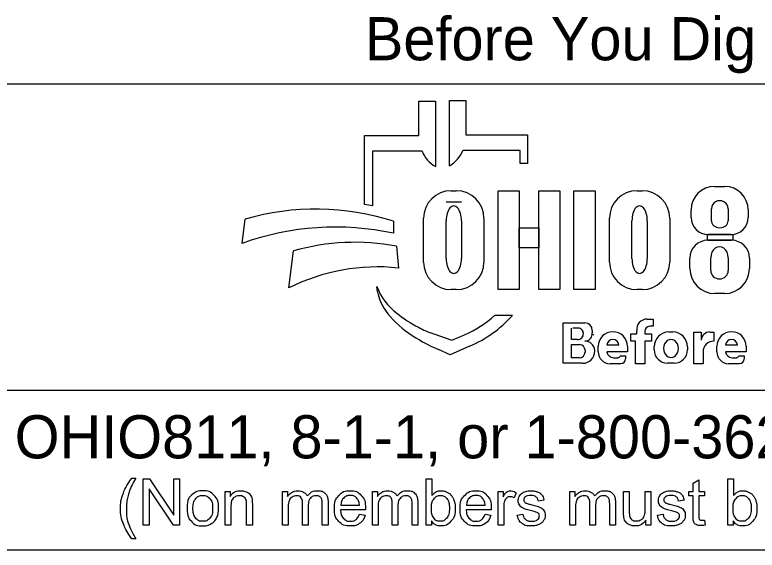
# Model space of a CAD drawing. Extents: x 0 to 34, y 0 to 22.
# Drawn here: x 2.423 to 4.831, y 2.143 to 3.88 of the extents above; entities that cross this region are included whole.
import ezdxf

# ---------------------------------------------------------------- set-up
doc = ezdxf.new("R2010")
doc.units = 0
doc.layers.add('SH_Data', color=7, linetype='Continuous')
doc.layers.add('SH_Text', color=7, linetype='Continuous')

msp = doc.modelspace()

# ---------------------------------------------------------------- linework, layer by layer
at = {"layer": 'SH_Data'}
for p, q in [((2.3775, 3.6553), (6.6275, 3.6553)), ((6.6275, 2.6607), (2.3775, 2.6607)), ((6.6275, 2.1428), (2.3775, 2.1428))]:
    msp.add_line(p, q, dxfattribs=at)
at = {"layer": 'SH_Text'}
for p, q in [((3.7335, 3.4883), (3.7335, 3.5998)), ((3.7335, 3.5998), (3.7872, 3.5998)), ((3.7872, 3.5998), (3.7872, 3.3877)), ((3.8329, 3.39), (3.8329, 3.6021)), ((3.8329, 3.6021), (3.8865, 3.6021)), ((3.8865, 3.6021), (3.8865, 3.4906)), ((3.5576, 3.2644), (3.5576, 3.4883)), ((3.5576, 3.4883), (3.7335, 3.4883)), ((3.8865, 3.4906), (4.0857, 3.4906)), ((4.0857, 3.4906), (4.0857, 3.3968)), ((3.5828, 3.4369), (3.5828, 3.26)), ((3.7439, 3.4369), (3.5828, 3.4369)), ((4.0625, 3.4392), (3.8761, 3.4392)), ((4.0625, 3.3968), (4.0625, 3.4392)), ((4.0857, 3.3968), (4.0625, 3.3968)), ((3.8385, 3.3091), (3.8551, 3.3091)), ((4.4416, 3.3091), (4.4581, 3.3091)), ((4.6931, 3.3231), (4.7258, 3.3231)), ((3.8718, 3.2721), (3.822, 3.2721)), ((4.6168, 3.2225), (4.6168, 3.2468)), ((4.683, 3.2111), (4.683, 3.2504)), ((4.7371, 3.2504), (4.7371, 3.2111)), ((4.8022, 3.2468), (4.8022, 3.2225)), ((3.1602, 3.1381), (3.1696, 3.2162)), ((3.6509, 3.2097), (3.6509, 3.1709)), ((3.7491, 3.0776), (3.7491, 3.2196)), ((3.822, 3.089), (3.822, 3.2114)), ((3.8718, 3.2114), (3.8718, 3.089)), ((3.9445, 3.2196), (3.9445, 3.0776)), ((4.3521, 3.0776), (4.3521, 3.2196)), ((4.425, 3.089), (4.425, 3.2114)), ((4.4748, 3.2114), (4.4748, 3.089)), ((4.5476, 3.2196), (4.5476, 3.0776)), ((4.7462, 3.1665), (4.6728, 3.1665)), ((4.671, 3.1482), (4.7483, 3.1482)), ((3.312, 2.9936), (3.3267, 3.1137)), ((3.6608, 3.1291), (3.6671, 3.0582)), ((4.6131, 3.0563), (4.6131, 3.0903)), ((4.6806, 3.0503), (4.6806, 3.0912)), ((4.7374, 3.0912), (4.7374, 3.0503)), ((4.8062, 3.0903), (4.8062, 3.0563)), ((3.5997, 2.9807), (3.5967, 2.9986)), ((3.8551, 2.9882), (3.8385, 2.9882)), ((4.4581, 2.9882), (4.4416, 2.9882)), ((4.7252, 2.9753), (4.6941, 2.9753)), ((3.98, 2.9048), (4.0375, 2.9048)), ((4.4739, 2.8926), (4.4934, 2.8926)), ((4.4934, 2.8926), (4.4934, 2.8696)), ((4.2013, 2.749), (4.2013, 2.8798)), ((4.2013, 2.8798), (4.2725, 2.8798)), ((4.4934, 2.8691), (4.4832, 2.8691)), ((3.7816, 2.8444), (3.841, 2.8239)), ((4.2293, 2.8263), (4.2293, 2.8632)), ((4.2545, 2.8632), (4.2332, 2.8632)), ((4.2963, 2.856), (4.2963, 2.8481)), ((4.4213, 2.8212), (4.4213, 2.8442)), ((4.4213, 2.8442), (4.4406, 2.8442)), ((4.4406, 2.8442), (4.4406, 2.8546)), ((4.4667, 2.8526), (4.4667, 2.8442)), ((4.4667, 2.8442), (4.4883, 2.8442)), ((4.4883, 2.8442), (4.4883, 2.8212)), ((4.5451, 2.8508), (4.5573, 2.8508)), ((4.6254, 2.7478), (4.6254, 2.8505)), ((4.6254, 2.8505), (4.6499, 2.8505)), ((4.6499, 2.8505), (4.6499, 2.8237)), ((4.6772, 2.8505), (4.691, 2.8505)), ((4.691, 2.8505), (4.691, 2.8209)), ((3.841, 2.8239), (3.8821, 2.8417)), ((4.2487, 2.8263), (4.2293, 2.8263)), ((4.4362, 2.8212), (4.4213, 2.8212)), ((4.4362, 2.7478), (4.4362, 2.8212)), ((4.4883, 2.8212), (4.4667, 2.8212)), ((4.4667, 2.8212), (4.4667, 2.7478)), ((3.8983, 2.8044), (3.835, 2.7769)), ((4.2293, 2.7669), (4.2293, 2.8097)), ((4.2293, 2.8097), (4.2548, 2.8097)), ((4.3159, 2.7858), (4.3159, 2.8042)), ((4.3824, 2.8082), (4.3439, 2.8082)), ((4.4104, 2.8042), (4.4104, 2.7866)), ((4.4973, 2.7922), (4.4973, 2.8029)), ((4.6051, 2.8029), (4.6051, 2.7922)), ((4.7008, 2.7858), (4.7008, 2.8042)), ((4.7674, 2.8082), (4.7288, 2.8082)), ((4.7953, 2.8042), (4.7953, 2.7866)), ((3.835, 2.7769), (3.7976, 2.7934)), ((4.2729, 2.7916), (4.2729, 2.7853)), ((4.3043, 2.7887), (4.3043, 2.7884)), ((4.4104, 2.7866), (4.344, 2.7866)), ((4.3876, 2.7729), (4.4045, 2.7729)), ((4.4045, 2.7729), (4.4045, 2.7631)), ((4.6559, 2.786), (4.6559, 2.7478)), ((4.7953, 2.7866), (4.7289, 2.7866)), ((4.7725, 2.7729), (4.7894, 2.7729)), ((4.7894, 2.7729), (4.7894, 2.7631)), ((4.265, 2.749), (4.2013, 2.749)), ((4.2546, 2.7669), (4.2293, 2.7669)), ((4.3892, 2.7478), (4.3538, 2.7478)), ((4.3649, 2.7673), (4.379, 2.7673)), ((4.4667, 2.7478), (4.4362, 2.7478)), ((4.5623, 2.7494), (4.5401, 2.7494)), ((4.6559, 2.7478), (4.6254, 2.7478)), ((4.7742, 2.7478), (4.7388, 2.7478)), ((4.7498, 2.7673), (4.7639, 2.7673))]:
    msp.add_line(p, q, dxfattribs=at)
for points in [[(3.991, 3.3081), (4.0589, 3.3081), (4.0589, 2.9881), (3.991, 2.9881)], [(4.1231, 3.3081), (4.1911, 3.3081), (4.1911, 2.9881), (4.1231, 2.9881)], [(4.2364, 3.3081), (4.3052, 3.3081), (4.3052, 2.9881), (4.2364, 2.9881)], [(4.0589, 3.1882), (4.1231, 3.1882), (4.1231, 3.1242), (4.0589, 3.1242)], [(4.6706, 3.1665), (4.7523, 3.1665), (4.7523, 3.1481), (4.6706, 3.1481)]]:
    msp.add_lwpolyline(points, close=True, dxfattribs=at)
for points in [[(2.8021, 2.3766), (2.8153, 2.3766)], [(2.8389, 2.2239), (2.8389, 2.3741), (2.8592, 2.3741), (2.9382, 2.2561), (2.9382, 2.3741), (2.9572, 2.3741), (2.9572, 2.2239), (2.9369, 2.2239), (2.8579, 2.3419), (2.8579, 2.2239), (2.8389, 2.2239)], [(3.7743, 2.2239), (3.7573, 2.2239), (3.7573, 2.3741), (3.7757, 2.3741), (3.7757, 2.3206)], [(4.6233, 2.2558), (4.6233, 2.3185), (4.6097, 2.3185), (4.6097, 2.3328), (4.6233, 2.3328), (4.6233, 2.3597), (4.6417, 2.3708), (4.6417, 2.3328), (4.6601, 2.3328), (4.6601, 2.3185), (4.6417, 2.3185), (4.6417, 2.2547)], [(4.7534, 2.2239), (4.7363, 2.2239), (4.7363, 2.3741), (4.7548, 2.3741), (4.7548, 2.3206)], [(3.1048, 2.2239), (3.1048, 2.3328), (3.1214, 2.3328), (3.1214, 2.3173)], [(3.2912, 2.2239), (3.2912, 2.3328), (3.3077, 2.3328), (3.3077, 2.3174)], [(3.5826, 2.2239), (3.5826, 2.3328), (3.5991, 2.3328), (3.5991, 2.3174)], [(3.9904, 2.2239), (3.9904, 2.3328), (4.007, 2.3328), (4.007, 2.3163)], [(4.0495, 2.3293), (4.043, 2.3122)], [(4.2236, 2.2239), (4.2236, 2.3328), (4.2401, 2.3328), (4.2401, 2.3174)], [(4.3979, 2.2654), (4.3979, 2.3328), (4.4164, 2.3328), (4.4164, 2.2724)], [(4.4676, 2.2745), (4.4676, 2.3328), (4.4861, 2.3328), (4.4861, 2.2239), (4.4696, 2.2239)], [(3.1932, 2.2908), (3.1932, 2.2239), (3.1748, 2.2239), (3.1748, 2.2901)], [(3.3743, 2.2871), (3.3743, 2.2239), (3.3559, 2.2239), (3.3559, 2.2946)], [(3.4388, 2.2986), (3.4388, 2.2239), (3.4203, 2.2239), (3.4203, 2.2924)], [(3.4799, 2.2887), (3.5406, 2.2887)], [(3.6657, 2.2871), (3.6657, 2.2239), (3.6473, 2.2239), (3.6473, 2.2946)], [(3.7301, 2.2986), (3.7301, 2.2239), (3.7117, 2.2239), (3.7117, 2.2924)], [(3.8879, 2.2887), (3.9486, 2.2887)], [(4.1394, 2.3046), (4.1213, 2.3022)], [(4.3067, 2.2871), (4.3067, 2.2239), (4.2883, 2.2239), (4.2883, 2.2946)], [(4.3711, 2.2986), (4.3711, 2.2239), (4.3527, 2.2239), (4.3527, 2.2924)], [(4.594, 2.3046), (4.5759, 2.3022)], [(3.1233, 2.2833), (3.1233, 2.2239), (3.1048, 2.2239)], [(3.3097, 2.2803), (3.3097, 2.2239), (3.2912, 2.2239)], [(3.56, 2.2736), (3.4788, 2.2736)], [(3.601, 2.2803), (3.601, 2.2239), (3.5826, 2.2239)], [(3.968, 2.2736), (3.8868, 2.2736)], [(4.0088, 2.2809), (4.0088, 2.2239), (3.9904, 2.2239)], [(4.242, 2.2803), (4.242, 2.2239), (4.2236, 2.2239)], [(3.5404, 2.2591), (3.5595, 2.2567)], [(3.9484, 2.2591), (3.9675, 2.2567)], [(4.053, 2.2564), (4.0712, 2.2593)], [(4.5076, 2.2564), (4.5258, 2.2593)], [(4.6601, 2.2404), (4.6628, 2.2241)], [(3.7743, 2.2375), (3.7743, 2.2239)], [(4.4696, 2.2239), (4.4696, 2.24)], [(4.7534, 2.2375), (4.7534, 2.2239)], [(2.8153, 2.1798), (2.8021, 2.1798)]]:
    msp.add_lwpolyline(points, dxfattribs=at)
for centre, radius, start, end in [((3.8353, 3.4736), 0.0985, 201.9296, 240.7469), ((3.7847, 3.476), 0.0985, 299.2531, 338.0704), ((3.8385, 3.2196), 0.0895, 90, 180), ((3.8551, 3.2196), 0.0895, 0, 90), ((4.4416, 3.2196), 0.0895, 90, 180), ((4.4581, 3.2196), 0.0895, 0, 90), ((4.6931, 3.2468), 0.0763, 90, 180), ((4.7258, 3.2468), 0.0763, 0, 90), ((3.4295, 2.4554), 0.8191, 79.2074, 81.0007), ((3.3997, 2.4302), 0.8191, 72.1402, 106.3144), ((4.6728, 3.2225), 0.056, 180, 270), ((4.7462, 3.2225), 0.056, 270, 0), ((3.4628, 2.2991), 0.8919, 77.8238, 109.8274), ((3.5267, 2.4094), 0.7322, 79.44, 105.8467), ((4.671, 3.0903), 0.0579, 90, 180), ((4.7483, 3.0903), 0.0579, 0, 90), ((3.5987, 2.4262), 0.6357, 83.8248, 116.8021), ((3.8385, 3.0776), 0.0895, 180, 270), ((3.8551, 3.0776), 0.0895, 270, 0), ((4.4416, 3.0776), 0.0895, 180, 270), ((4.4581, 3.0776), 0.0895, 270, 0), ((4.6941, 3.0563), 0.081, 180, 270), ((4.7252, 3.0563), 0.081, 270, 0), ((3.7841, 3.0707), 0.2008, 201.0457, 232.5314), ((3.741, 3.0048), 0.1433, 189.6817, 216.0884), ((3.8747, 3.1022), 0.3088, 216.0884, 235.7167), ((3.9766, 3.3219), 0.5173, 232.5314, 241.794), ((3.7387, 3.1722), 0.3602, 293.4582, 312.0712), ((3.7387, 3.1722), 0.401, 293.4582, 317.8286), ((4.4739, 2.859), 0.0335, 90, 187.5187), ((4.2725, 2.856), 0.0238, 0, 90), ((4.4832, 2.8526), 0.0165, 90, 180), ((4.0412, 3.3465), 0.6044, 235.7167, 246.2325), ((3.8914, 3.1631), 0.3371, 241.794, 250.9821), ((4.2487, 2.845), 0.0187, 270, 2.0582), ((4.2505, 2.8463), 0.0169, 357.8325, 90), ((4.2721, 2.8453), 0.0243, 270, 6.6529), ((4.2827, 2.8438), 0.0175, 347.4023, 0), ((4.3631, 2.8042), 0.0473, 0, 180), ((4.5451, 2.8029), 0.0478, 90, 180), ((4.5573, 2.8029), 0.0478, 0, 90), ((4.6768, 2.8237), 0.0269, 89.2449, 180), ((4.7481, 2.8042), 0.0473, 0, 180), ((4.2722, 2.7889), 0.0321, 4.0748, 90), ((4.3632, 2.8072), 0.0193, 2.9632, 177.0368), ((4.6908, 2.786), 0.0349, 89.6033, 180), ((4.7481, 2.8072), 0.0193, 2.9632, 177.0368), ((4.2548, 2.7916), 0.0181, 0, 90), ((4.2714, 2.7887), 0.033, 0, 11.7502), ((4.2546, 2.7853), 0.0184, 270, 0), ((4.265, 2.7884), 0.0393, 270, 0), ((4.3538, 2.7858), 0.038, 180, 270), ((4.3649, 2.7883), 0.021, 184.827, 270), ((4.379, 2.7767), 0.00938, 270, 335.9979), ((4.5401, 2.7922), 0.0428, 180, 270), ((4.5623, 2.7922), 0.0428, 270, 0), ((4.7388, 2.7858), 0.038, 180, 270), ((4.7498, 2.7883), 0.021, 184.827, 270), ((4.7639, 2.7767), 0.00938, 270, 335.9979), ((4.3892, 2.7631), 0.0152, 270, 0), ((4.7742, 2.7631), 0.0152, 270, 0)]:
    msp.add_arc(centre, radius, start, end, dxfattribs=at)
for centre, major_axis, ratio, start_param, end_param in [((4.71, 3.2504), (0.0271, 0), 0.969373, 0, 3.141593), ((3.8469, 3.2114), (0, 0.0484), 0.514403, 4.712389, 7.853982), ((4.4499, 3.2114), (0, 0.0484), 0.514403, 4.712389, 7.853982), ((4.71, 3.2111), (0.0271, 0), 0.818453, 3.141593, 6.283185), ((4.709, 3.0912), (0, 0.0358), 0.794529, 4.712389, 7.853982), ((3.8469, 3.089), (0, 0.0484), 0.514403, 1.570796, 4.712389), ((4.4499, 3.089), (0, 0.0484), 0.514403, 1.570796, 4.712389), ((4.709, 3.0503), (0.0284, 0), 0.959837, 3.141593, 6.283185), ((4.5517, 2.7976), (0, 0.029), 0.832186, 4.712389, 7.853982), ((4.5517, 2.7976), (0, 0.0302), 0.797287, 1.570796, 4.712389)]:
    msp.add_ellipse(centre, major_axis=major_axis, ratio=ratio, start_param=start_param, end_param=end_param, dxfattribs=at)
for points in [[(2.8021, 2.1798), (2.7869, 2.199), (2.7763, 2.2248), (2.7657, 2.2506), (2.7657, 2.2783), (2.7657, 2.3026), (2.7736, 2.325), (2.7829, 2.3509), (2.8021, 2.3766)], [(2.8153, 2.3766), (2.8029, 2.3553), (2.7989, 2.3462), (2.7927, 2.332), (2.7891, 2.3167), (2.7847, 2.2975), (2.7847, 2.2782), (2.7847, 2.2289), (2.8153, 2.1798)], [(2.9814, 2.2783), (2.9814, 2.3085), (2.9981, 2.3231), (3.0122, 2.3352), (3.0323, 2.3352), (3.0547, 2.3352), (3.069, 2.3205), (3.0832, 2.3058), (3.0832, 2.2799), (3.0832, 2.2589), (3.0769, 2.2469), (3.0706, 2.2348), (3.0586, 2.2282), (3.0466, 2.2215), (3.0323, 2.2215), (3.0095, 2.2215), (2.9954, 2.2362), (2.9814, 2.2508), (2.9814, 2.2783)], [(3.0003, 2.2783), (3.0003, 2.2574), (3.0094, 2.247), (3.0185, 2.2366), (3.0323, 2.2366), (3.046, 2.2366), (3.0551, 2.2471), (3.0642, 2.2575), (3.0642, 2.279), (3.0642, 2.2991), (3.0551, 2.3095), (3.0459, 2.3199), (3.0323, 2.3199), (3.0185, 2.3199), (3.0094, 2.3096), (3.0003, 2.2992), (3.0003, 2.2783)], [(3.1214, 2.3173), (3.1334, 2.3352), (3.156, 2.3352), (3.1659, 2.3352), (3.1741, 2.3316), (3.1823, 2.3281), (3.1864, 2.3224), (3.1905, 2.3166), (3.1922, 2.3087), (3.1932, 2.3036), (3.1932, 2.2908)], [(3.1748, 2.2901), (3.1748, 2.3013), (3.1726, 2.3069), (3.1705, 2.3125), (3.165, 2.3158), (3.1595, 2.3191), (3.1521, 2.3191), (3.1404, 2.3191), (3.1318, 2.3117), (3.1233, 2.3042), (3.1233, 2.2833)], [(3.3077, 2.3174), (3.3128, 2.3254), (3.3214, 2.3303), (3.3299, 2.3352), (3.3407, 2.3352), (3.3528, 2.3352), (3.3606, 2.3301), (3.3683, 2.3251), (3.3715, 2.3161), (3.3844, 2.3352), (3.4051, 2.3352), (3.4213, 2.3352), (3.43, 2.3262), (3.4388, 2.3172), (3.4388, 2.2986)], [(3.3559, 2.2946), (3.3559, 2.3069), (3.3514, 2.313), (3.3469, 2.3191), (3.3366, 2.3191), (3.3288, 2.3191), (3.3222, 2.315), (3.3156, 2.311), (3.3126, 2.3031), (3.3097, 2.2952), (3.3097, 2.2803)], [(3.4203, 2.2924), (3.4203, 2.3035), (3.4185, 2.3083), (3.4168, 2.3132), (3.412, 2.3162), (3.4073, 2.3191), (3.401, 2.3191), (3.3895, 2.3191), (3.3819, 2.3115), (3.3743, 2.3039), (3.3743, 2.2871)], [(3.5595, 2.2567), (3.555, 2.24), (3.5428, 2.2307), (3.5306, 2.2215), (3.5117, 2.2215), (3.4878, 2.2215), (3.4738, 2.2362), (3.4598, 2.2509), (3.4598, 2.2774), (3.4598, 2.3049), (3.474, 2.32), (3.4881, 2.3352), (3.5106, 2.3352), (3.5324, 2.3352), (3.5463, 2.3203), (3.5601, 2.3055), (3.5601, 2.2785), (3.5601, 2.2769), (3.56, 2.2736)], [(3.5406, 2.2887), (3.5394, 2.3025), (3.5337, 2.3094), (3.5249, 2.3201), (3.5108, 2.3201), (3.4981, 2.3201), (3.4894, 2.3115), (3.4808, 2.303), (3.4799, 2.2887)], [(3.5991, 2.3174), (3.6042, 2.3254), (3.6127, 2.3303), (3.6212, 2.3352), (3.6321, 2.3352), (3.6442, 2.3352), (3.6519, 2.3301), (3.6597, 2.3251), (3.6628, 2.3161), (3.6758, 2.3352), (3.6965, 2.3352), (3.7127, 2.3352), (3.7214, 2.3262), (3.7301, 2.3172), (3.7301, 2.2986)], [(3.6473, 2.2946), (3.6473, 2.3069), (3.6428, 2.313), (3.6383, 2.3191), (3.628, 2.3191), (3.6202, 2.3191), (3.6136, 2.315), (3.607, 2.311), (3.604, 2.3031), (3.601, 2.2952), (3.601, 2.2803)], [(3.7117, 2.2924), (3.7117, 2.3035), (3.7099, 2.3083), (3.7081, 2.3132), (3.7034, 2.3162), (3.6987, 2.3191), (3.6923, 2.3191), (3.6809, 2.3191), (3.6733, 2.3115), (3.6657, 2.3039), (3.6657, 2.2871)], [(3.7741, 2.2792), (3.7741, 2.2596), (3.7794, 2.2509), (3.7881, 2.2366), (3.8029, 2.2366), (3.815, 2.2366), (3.8238, 2.2471), (3.8326, 2.2576), (3.8326, 2.2784), (3.8326, 2.2998), (3.8241, 2.3099), (3.8157, 2.3201), (3.8038, 2.3201), (3.7917, 2.3201), (3.7829, 2.3096), (3.7741, 2.299), (3.7741, 2.2792)], [(3.7757, 2.3206), (3.7874, 2.3352), (3.8055, 2.3352), (3.8155, 2.3352), (3.8245, 2.3311), (3.8335, 2.3271), (3.8392, 2.3198), (3.845, 2.3124), (3.8483, 2.3021), (3.8516, 2.2918), (3.8516, 2.28), (3.8516, 2.252), (3.8378, 2.2368), (3.8239, 2.2215), (3.8046, 2.2215), (3.7853, 2.2215), (3.7743, 2.2375)], [(3.9675, 2.2567), (3.963, 2.24), (3.9508, 2.2307), (3.9386, 2.2215), (3.9196, 2.2215), (3.8958, 2.2215), (3.8818, 2.2362), (3.8678, 2.2509), (3.8678, 2.2774), (3.8678, 2.3049), (3.882, 2.32), (3.8961, 2.3352), (3.9186, 2.3352), (3.9404, 2.3352), (3.9543, 2.3203), (3.9681, 2.3055), (3.9681, 2.2785), (3.9681, 2.2769), (3.968, 2.2736)], [(3.9486, 2.2887), (3.9474, 2.3025), (3.9417, 2.3094), (3.9328, 2.3201), (3.9188, 2.3201), (3.9061, 2.3201), (3.8974, 2.3115), (3.8888, 2.303), (3.8879, 2.2887)], [(4.007, 2.3163), (4.0133, 2.3278), (4.0187, 2.3315), (4.0241, 2.3352), (4.0305, 2.3352), (4.0398, 2.3352), (4.0495, 2.3293)], [(4.043, 2.3122), (4.0363, 2.3162), (4.0295, 2.3162), (4.0235, 2.3162), (4.0187, 2.3125), (4.0139, 2.3089), (4.0119, 2.3024), (4.0088, 2.2926), (4.0088, 2.2809)], [(4.1213, 2.3022), (4.1201, 2.3106), (4.1142, 2.3153), (4.1083, 2.3201), (4.0975, 2.3201), (4.0848, 2.3201), (4.0794, 2.3159), (4.0739, 2.3116), (4.0739, 2.306), (4.0739, 2.3024), (4.0762, 2.2995), (4.0785, 2.2966), (4.0833, 2.2946), (4.086, 2.2936), (4.0996, 2.2899), (4.1192, 2.2847), (4.1269, 2.2813), (4.1347, 2.278), (4.1391, 2.2717), (4.1435, 2.2653), (4.1435, 2.2559), (4.1435, 2.2467), (4.1381, 2.2386), (4.1327, 2.2304), (4.1226, 2.226), (4.1124, 2.2215), (4.0996, 2.2215), (4.0784, 2.2215), (4.0672, 2.2303), (4.0561, 2.2391), (4.053, 2.2564)], [(4.0712, 2.2593), (4.0727, 2.2483), (4.0798, 2.2425), (4.0868, 2.2366), (4.0995, 2.2366), (4.1122, 2.2366), (4.1184, 2.2418), (4.1245, 2.247), (4.1245, 2.254), (4.1245, 2.2602), (4.1191, 2.2638), (4.1153, 2.2663), (4.1002, 2.2701), (4.0799, 2.2752), (4.072, 2.2789), (4.0642, 2.2827), (4.0601, 2.2893), (4.0561, 2.2959), (4.0561, 2.3038), (4.0561, 2.3111), (4.0594, 2.3173), (4.0628, 2.3235), (4.0685, 2.3276), (4.0728, 2.3308), (4.0803, 2.333), (4.0877, 2.3352), (4.0962, 2.3352), (4.109, 2.3352), (4.1187, 2.3315), (4.1284, 2.3278), (4.133, 2.3215), (4.1377, 2.3152), (4.1394, 2.3046)], [(4.2401, 2.3174), (4.2452, 2.3254), (4.2537, 2.3303), (4.2622, 2.3352), (4.2731, 2.3352), (4.2852, 2.3352), (4.2929, 2.3301), (4.3007, 2.3251), (4.3038, 2.3161), (4.3168, 2.3352), (4.3375, 2.3352), (4.3537, 2.3352), (4.3624, 2.3262), (4.3711, 2.3172), (4.3711, 2.2986)], [(4.2883, 2.2946), (4.2883, 2.3069), (4.2838, 2.313), (4.2793, 2.3191), (4.269, 2.3191), (4.2612, 2.3191), (4.2546, 2.315), (4.248, 2.311), (4.245, 2.3031), (4.242, 2.2952), (4.242, 2.2803)], [(4.3527, 2.2924), (4.3527, 2.3035), (4.3509, 2.3083), (4.3491, 2.3132), (4.3444, 2.3162), (4.3397, 2.3191), (4.3333, 2.3191), (4.3219, 2.3191), (4.3143, 2.3115), (4.3067, 2.3039), (4.3067, 2.2871)], [(4.5759, 2.3022), (4.5747, 2.3106), (4.5688, 2.3153), (4.5629, 2.3201), (4.5521, 2.3201), (4.5394, 2.3201), (4.5339, 2.3159), (4.5285, 2.3116), (4.5285, 2.306), (4.5285, 2.3024), (4.5308, 2.2995), (4.533, 2.2966), (4.5378, 2.2946), (4.5406, 2.2936), (4.5542, 2.2899), (4.5737, 2.2847), (4.5815, 2.2813), (4.5893, 2.278), (4.5937, 2.2717), (4.5981, 2.2653), (4.5981, 2.2559), (4.5981, 2.2467), (4.5927, 2.2386), (4.5873, 2.2304), (4.5772, 2.226), (4.567, 2.2215), (4.5542, 2.2215), (4.5329, 2.2215), (4.5218, 2.2303), (4.5107, 2.2391), (4.5076, 2.2564)], [(4.5258, 2.2593), (4.5273, 2.2483), (4.5343, 2.2425), (4.5414, 2.2366), (4.554, 2.2366), (4.5668, 2.2366), (4.5729, 2.2418), (4.5791, 2.247), (4.5791, 2.254), (4.5791, 2.2602), (4.5736, 2.2638), (4.5698, 2.2663), (4.5548, 2.2701), (4.5345, 2.2752), (4.5266, 2.2789), (4.5188, 2.2827), (4.5147, 2.2893), (4.5107, 2.2959), (4.5107, 2.3038), (4.5107, 2.3111), (4.514, 2.3173), (4.5173, 2.3235), (4.5231, 2.3276), (4.5274, 2.3308), (4.5348, 2.333), (4.5423, 2.3352), (4.5508, 2.3352), (4.5636, 2.3352), (4.5733, 2.3315), (4.583, 2.3278), (4.5876, 2.3215), (4.5922, 2.3152), (4.594, 2.3046)], [(4.7532, 2.2792), (4.7532, 2.2596), (4.7585, 2.2509), (4.7672, 2.2366), (4.782, 2.2366), (4.7941, 2.2366), (4.8029, 2.2471), (4.8116, 2.2576), (4.8116, 2.2784), (4.8116, 2.2998), (4.8032, 2.3099), (4.7948, 2.3201), (4.7828, 2.3201), (4.7708, 2.3201), (4.762, 2.3096), (4.7532, 2.299), (4.7532, 2.2792)], [(4.7548, 2.3206), (4.7664, 2.3352), (4.7846, 2.3352), (4.7946, 2.3352), (4.8036, 2.3311), (4.8125, 2.3271), (4.8183, 2.3198), (4.8241, 2.3124), (4.8274, 2.3021), (4.8306, 2.2918), (4.8306, 2.28), (4.8306, 2.252), (4.8168, 2.2368), (4.803, 2.2215), (4.7836, 2.2215), (4.7644, 2.2215), (4.7534, 2.2375)], [(3.4788, 2.2736), (3.4799, 2.2557), (3.489, 2.2462), (3.4981, 2.2366), (3.5117, 2.2366), (3.5219, 2.2366), (3.5291, 2.242), (3.5362, 2.2473), (3.5404, 2.2591)], [(3.8868, 2.2736), (3.8879, 2.2557), (3.897, 2.2462), (3.9061, 2.2366), (3.9197, 2.2366), (3.9299, 2.2366), (3.937, 2.242), (3.9442, 2.2473), (3.9484, 2.2591)], [(4.4696, 2.24), (4.4569, 2.2215), (4.4351, 2.2215), (4.4255, 2.2215), (4.4171, 2.2252), (4.4088, 2.2289), (4.4047, 2.2345), (4.4007, 2.2401), (4.3991, 2.2482), (4.3979, 2.2536), (4.3979, 2.2654)], [(4.4164, 2.2724), (4.4164, 2.258), (4.4175, 2.253), (4.4192, 2.2457), (4.4249, 2.2416), (4.4305, 2.2374), (4.4388, 2.2374), (4.4471, 2.2374), (4.4543, 2.2417), (4.4616, 2.2459), (4.4646, 2.2533), (4.4676, 2.2606), (4.4676, 2.2745)], [(4.6628, 2.2241), (4.655, 2.2224), (4.6488, 2.2224), (4.6388, 2.2224), (4.6333, 2.2256), (4.6278, 2.2288), (4.6255, 2.234), (4.6233, 2.2392), (4.6233, 2.2558)], [(4.6417, 2.2547), (4.6417, 2.2468), (4.6427, 2.2445), (4.6436, 2.2423), (4.6458, 2.2409), (4.648, 2.2396), (4.6521, 2.2396), (4.6551, 2.2396), (4.6601, 2.2404)]]:
    msp.add_open_spline(points, degree=3, dxfattribs=at)

# ---------------------------------------------------------------- texts
for s, p in [('Before You Dig', (3.5583, 3.7321)), ('OHIO811, 8-1-1, or 1-800-362-2764', (2.422, 2.4406))]:
    msp.add_text(s, height=0.14, dxfattribs=at).set_placement(p)

doc.saveas('drawing.dxf')
